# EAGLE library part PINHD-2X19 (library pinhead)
PIN HEADER
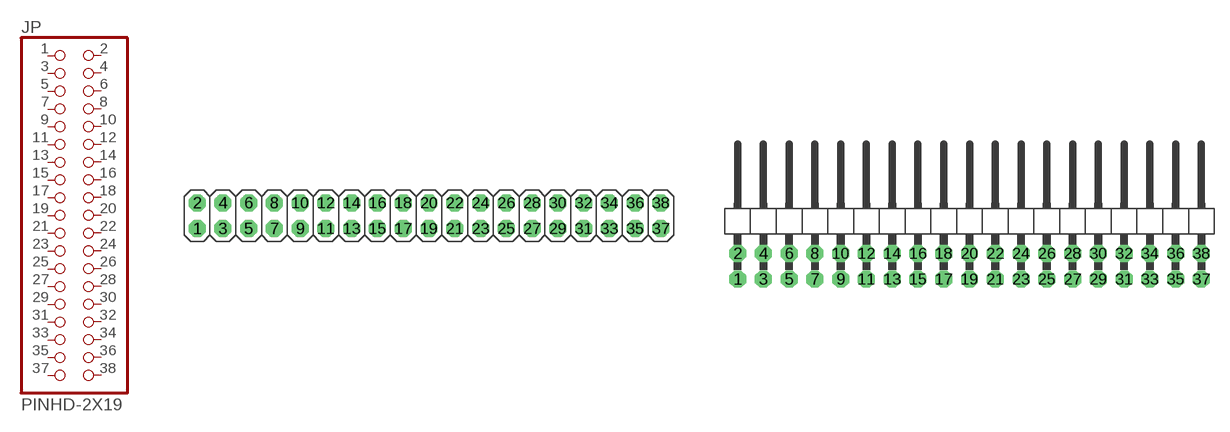
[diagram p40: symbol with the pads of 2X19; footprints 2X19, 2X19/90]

Designator prefix JP

## PINHD-2X19  [2X19]
1  1  pas
2  2  pas
3  3  pas
4  4  pas
5  5  pas
6  6  pas
7  7  pas
8  8  pas
9  9  pas
10  10  pas
11  11  pas
12  12  pas
13  13  pas
14  14  pas
15  15  pas
16  16  pas
17  17  pas
18  18  pas
19  19  pas
20  20  pas
21  21  pas
22  22  pas
23  23  pas
24  24  pas
25  25  pas
26  26  pas
27  27  pas
28  28  pas
29  29  pas
30  30  pas
31  31  pas
32  32  pas
33  33  pas
34  34  pas
35  35  pas
36  36  pas
37  37  pas
38  38  pas

## PINHD-2X19/90  [2X19/90]
Pads as for 2X19

## Footprint 2X19 (pad centres in mm)
PIN HEADER
drill 1.016 pad 1.67 octagon: 1 -22.86,-1.27; 2 -22.86,1.27; 3 -20.32,-1.27; 4 -20.32,1.27; 5 -17.78,-1.27; 6 -17.78,1.27; 7 -15.24,-1.27; 8 -15.24,1.27; 9 -12.7,-1.27; 10 -12.7,1.27; 11 -10.16,-1.27; 12 -10.16,1.27; 13 -7.62,-1.27; 14 -7.62,1.27; 15 -5.08,-1.27; 16 -5.08,1.27; 17 -2.54,-1.27; 18 -2.54,1.27; 19 0,-1.27; 20 0,1.27; 21 2.54,-1.27; 22 2.54,1.27; 23 5.08,-1.27; 24 5.08,1.27; 25 7.62,-1.27; 26 7.62,1.27; 27 10.16,-1.27; 28 10.16,1.27; 29 12.7,-1.27; 30 12.7,1.27; 31 15.24,-1.27; 32 15.24,1.27; 33 17.78,-1.27; 34 17.78,1.27; 35 20.32,-1.27; 36 20.32,1.27; 37 22.86,-1.27; 38 22.86,1.27

## Footprint 2X19/90 (pad centres in mm)
PIN HEADER
drill 1.016 pad 1.67 octagon: 1 -22.86,-6.35; 2 -22.86,-3.81; 3 -20.32,-6.35; 4 -20.32,-3.81; 5 -17.78,-6.35; 6 -17.78,-3.81; 7 -15.24,-6.35; 8 -15.24,-3.81; 9 -12.7,-6.35; 10 -12.7,-3.81; 11 -10.16,-6.35; 12 -10.16,-3.81; 13 -7.62,-6.35; 14 -7.62,-3.81; 15 -5.08,-6.35; 16 -5.08,-3.81; 17 -2.54,-6.35; 18 -2.54,-3.81; 19 0,-6.35; 20 0,-3.81; 21 2.54,-6.35; 22 2.54,-3.81; 23 5.08,-6.35; 24 5.08,-3.81; 25 7.62,-6.35; 26 7.62,-3.81; 27 10.16,-6.35; 28 10.16,-3.81; 29 12.7,-6.35; 30 12.7,-3.81; 31 15.24,-6.35; 32 15.24,-3.81; 33 17.78,-6.35; 34 17.78,-3.81; 35 20.32,-6.35; 36 20.32,-3.81; 37 22.86,-6.35; 38 22.86,-3.81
